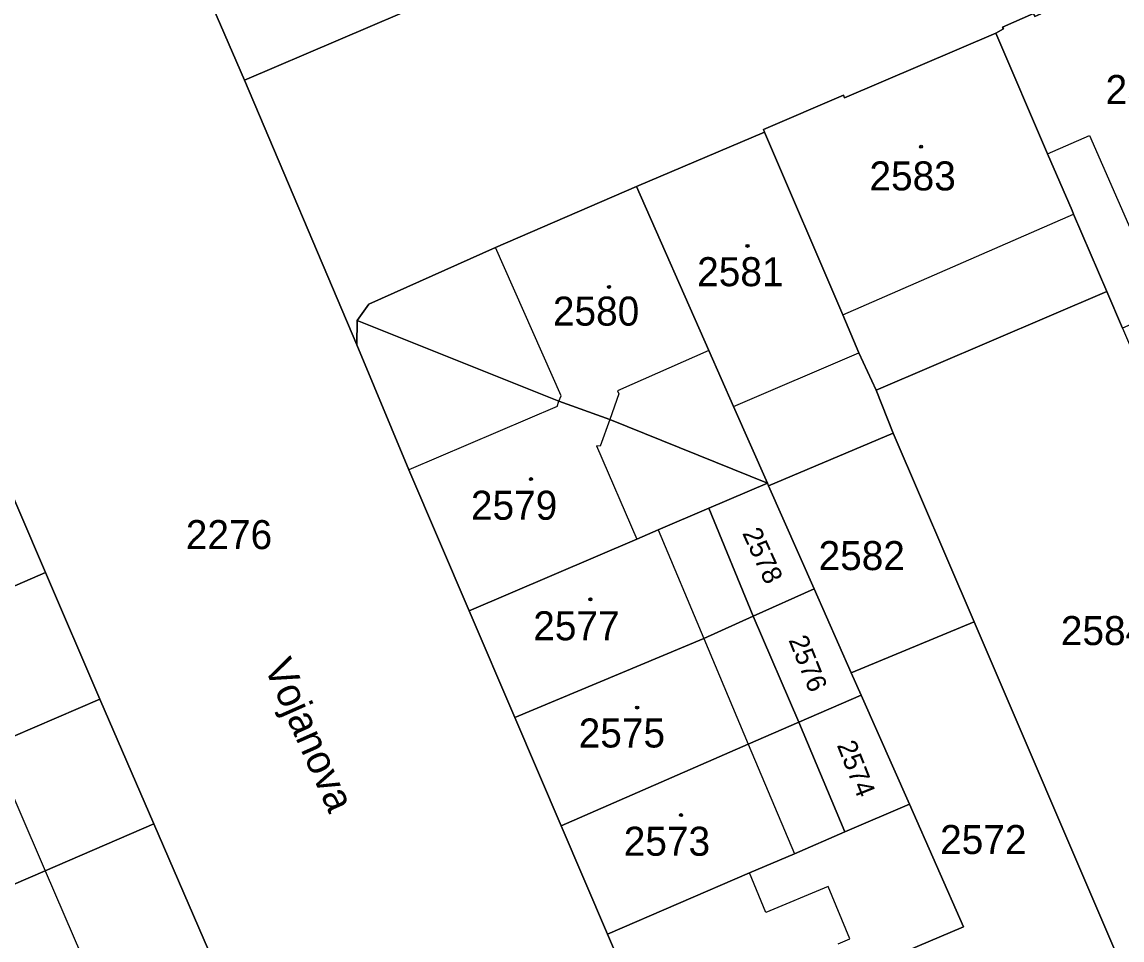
# Model space of a CAD drawing. Extents: x -596233 to -595156, y -1161235 to -1159375.
# Drawn here: x -595851.8 to -595787.4, y -1160619.4 to -1160565.6 of the extents above; entities that cross this region are included whole.
import ezdxf

# ---------------------------------------------------------------- set-up
doc = ezdxf.new("R2010")
doc.units = 0
for name, color, linetype in [('KN_CAR_KR', 7, 'Continuous'), ('KN_KULTURY', 7, 'Continuous'), ('KN_PARC_CIS_POZ', 7, 'Continuous'), ('KN_PARC_CIS_STAV', 7, 'Continuous'), ('KN_PARC_PLOCHA', 7, 'Continuous'), ('KN_ULICE', 7, 'Continuous'), ('parcely_l', 7, 'Continuous')]:
    doc.layers.add(name, color=color, linetype=linetype)

msp = doc.modelspace()

# ---------------------------------------------------------------- linework, layer by layer
at = {"layer": 'KN_CAR_KR'}
for points in [[(-595791.74, -1160573.35), (-595789.28, -1160572.29)], [(-595789.28, -1160572.29), (-595786.87, -1160577.8)], [(-595803.74, -1160582.79), (-595790.22, -1160576.89)], [(-595820.24, -1160587.53), (-595824.08, -1160578.85)], [(-595811.58, -1160584.87), (-595816.93, -1160587.23)], [(-595810.13, -1160588.16), (-595802.79, -1160585.02)], [(-595816.93, -1160587.23), (-595816.85, -1160587.41)], [(-595820.47, -1160588.15), (-595820.36, -1160587.84)], [(-595820.36, -1160587.84), (-595820.24, -1160587.53)], [(-595816.85, -1160587.41), (-595817.39, -1160588.92)], [(-595820.47, -1160588.15), (-595829.16, -1160591.86)], [(-595817.39, -1160588.92), (-595817.94, -1160590.47)], [(-595817.94, -1160590.47), (-595818.16, -1160590.46)], [(-595818.16, -1160590.46), (-595815.81, -1160595.93)], [(-595814.55, -1160595.38), (-595811.88, -1160601.75)], [(-595811.88, -1160601.75), (-595809.27, -1160607.94)], [(-595809.27, -1160607.94), (-595806.57, -1160614.35)], [(-595853.61, -1160608.04), (-595850.46, -1160615.35)], [(-595850.46, -1160615.35), (-595847.24, -1160622.83)], [(-595808.25, -1160617.79), (-595809.21, -1160615.48)], [(-595804.59, -1160616.27), (-595808.25, -1160617.79)], [(-595803.32, -1160619.34), (-595804.59, -1160616.27)], [(-595804, -1160619.62), (-595803.32, -1160619.34)]]:
    msp.add_lwpolyline(points, dxfattribs=at)
at = {"layer": 'KN_KULTURY'}
for centre, radius in [((-595799.15, -1160572.94), 0.09), ((-595799.15, -1160572.94), 0.0398), ((-595809.32, -1160578.75), 0.09), ((-595809.32, -1160578.75), 0.0398), ((-595817.43, -1160581.15), 0.09), ((-595817.43, -1160581.15), 0.0398), ((-595822, -1160592.41), 0.09), ((-595822, -1160592.41), 0.0398), ((-595818.52, -1160599.45), 0.09), ((-595818.52, -1160599.45), 0.0398), ((-595815.78, -1160605.79), 0.09), ((-595815.78, -1160605.79), 0.0398), ((-595813.21, -1160612.09), 0.09), ((-595813.21, -1160612.09), 0.0398)]:
    msp.add_circle(centre, radius, dxfattribs=at)
at = {"layer": 'KN_PARC_PLOCHA'}
for points in [[(-595828.6, -1160546.22), (-595824.7, -1160554.71), (-595830.71, -1160557.42), (-595827.81, -1160564.34), (-595838.78, -1160569.04), (-595848.56, -1160546.48), (-595844.18, -1160544.58), (-595838.57, -1160542.19), (-595839.89, -1160539.16), (-595839.66, -1160539.06), (-595843.45, -1160530.21), (-595843.18, -1160530.1), (-595844.25, -1160527.51), (-595840.67, -1160526.1), (-595846.8, -1160512.82), (-595844.83, -1160511.87)], [(-595773.74, -1160576.54), (-595773.38, -1160577.4), (-595787.35, -1160583.57), (-595788.27, -1160581.43), (-595790.22, -1160576.89), (-595790.31, -1160576.67), (-595791.74, -1160573.35), (-595794.77, -1160566.29), (-595794.33, -1160566.04), (-595794.38, -1160565.93), (-595792.56, -1160565.14), (-595792.49, -1160565.31), (-595792.13, -1160565.16), (-595792.2, -1160564.99), (-595785.13, -1160561.88), (-595785.06, -1160562.03), (-595780.8, -1160560.17), (-595775.75, -1160571.89)], [(-595788.27, -1160581.43), (-595801.78, -1160587.2), (-595802.79, -1160585.02), (-595803.74, -1160582.79), (-595808.33, -1160572.08), (-595808.39, -1160571.94), (-595803.7, -1160569.93), (-595803.64, -1160570.07), (-595794.77, -1160566.29), (-595791.74, -1160573.35), (-595790.31, -1160576.67), (-595790.22, -1160576.89)], [(-595801.78, -1160587.2), (-595800.78, -1160589.71), (-595808.08, -1160592.8), (-595808.15, -1160592.64), (-595810.13, -1160588.16), (-595811.58, -1160584.87), (-595815.82, -1160575.28), (-595808.33, -1160572.08), (-595803.74, -1160582.79), (-595802.79, -1160585.02)], [(-595808.15, -1160592.64), (-595817.39, -1160588.92), (-595820.36, -1160587.84), (-595832.18, -1160583.11), (-595831.5, -1160582.16), (-595824.08, -1160578.85), (-595815.82, -1160575.28), (-595811.58, -1160584.87), (-595810.13, -1160588.16)], [(-595787.35, -1160583.57), (-595774.09, -1160614.44), (-595785.74, -1160619.46), (-595787.69, -1160620.28), (-595796.04, -1160600.77), (-595800.78, -1160589.71), (-595801.78, -1160587.2), (-595788.27, -1160581.43)], [(-595808.15, -1160592.64), (-595811.59, -1160594.11), (-595814.55, -1160595.38), (-595815.81, -1160595.93), (-595825.62, -1160600.13), (-595829.16, -1160591.86), (-595832.2, -1160584.55), (-595832.18, -1160583.11), (-595820.36, -1160587.84), (-595817.39, -1160588.92)], [(-595796.04, -1160600.77), (-595803.24, -1160603.75), (-595805.41, -1160598.83), (-595808.08, -1160592.8), (-595800.78, -1160589.71)], [(-595850.43, -1160597.88), (-595856.78, -1160600.64), (-595865.21, -1160604.3), (-595868.97, -1160605.93), (-595871.65, -1160598.48), (-595868.26, -1160597), (-595859.91, -1160593.35), (-595853.57, -1160590.58)], [(-595808.08, -1160592.8), (-595805.41, -1160598.83), (-595808.98, -1160600.44), (-595811.59, -1160594.11), (-595808.15, -1160592.64)], [(-595808.98, -1160600.44), (-595811.88, -1160601.75), (-595822.95, -1160606.37), (-595825.62, -1160600.13), (-595815.81, -1160595.93), (-595814.55, -1160595.38), (-595811.59, -1160594.11)], [(-595847.25, -1160605.29), (-595853.61, -1160608.04), (-595862.1, -1160611.7), (-595866.23, -1160613.48), (-595869.29, -1160606.07), (-595868.97, -1160605.93), (-595865.21, -1160604.3), (-595856.78, -1160600.64), (-595850.43, -1160597.88)], [(-595803.24, -1160603.75), (-595802.66, -1160605.06), (-595806.32, -1160606.65), (-595808.98, -1160600.44), (-595805.41, -1160598.83)], [(-595806.32, -1160606.65), (-595809.27, -1160607.94), (-595820.24, -1160612.71), (-595822.95, -1160606.37), (-595811.88, -1160601.75), (-595808.98, -1160600.44)], [(-595787.69, -1160620.28), (-595797.48, -1160624.38), (-595801.35, -1160626), (-595803.25, -1160621.42), (-595796.66, -1160618.63), (-595799.84, -1160611.45), (-595802.66, -1160605.06), (-595803.24, -1160603.75), (-595796.04, -1160600.77)], [(-595844.08, -1160612.6), (-595850.46, -1160615.35), (-595858.89, -1160618.98), (-595863.02, -1160620.76), (-595866.23, -1160613.48), (-595862.1, -1160611.7), (-595853.61, -1160608.04), (-595847.25, -1160605.29)], [(-595799.84, -1160611.45), (-595803.61, -1160613.07), (-595806.32, -1160606.65), (-595802.66, -1160605.06)], [(-595803.61, -1160613.07), (-595806.57, -1160614.35), (-595809.21, -1160615.48), (-595817.52, -1160619.06), (-595820.24, -1160612.71), (-595809.27, -1160607.94), (-595806.32, -1160606.65)], [(-595801.35, -1160626), (-595801.57, -1160626.1), (-595802.5, -1160626.5), (-595812.49, -1160630.81), (-595817.52, -1160619.06), (-595809.21, -1160615.48), (-595806.57, -1160614.35), (-595803.61, -1160613.07), (-595799.84, -1160611.45), (-595796.66, -1160618.63), (-595803.25, -1160621.42)], [(-595840.89, -1160620), (-595847.24, -1160622.83), (-595855.67, -1160626.59), (-595858.09, -1160627.67), (-595859.78, -1160628.38), (-595863.02, -1160620.76), (-595858.89, -1160618.98), (-595850.46, -1160615.35), (-595844.08, -1160612.6)]]:
    msp.add_lwpolyline(points, close=True, dxfattribs=at)
for points in [[(-595853.68, -1160534.62), (-595849.94, -1160543.33), (-595848.56, -1160546.48), (-595838.78, -1160569.04), (-595832.2, -1160584.55), (-595829.16, -1160591.86), (-595825.62, -1160600.13), (-595822.95, -1160606.37), (-595820.24, -1160612.71), (-595817.52, -1160619.06), (-595812.49, -1160630.81)], [(-595792.56, -1160565.14), (-595794.38, -1160565.93), (-595794.33, -1160566.04), (-595794.77, -1160566.29), (-595803.64, -1160570.07), (-595803.7, -1160569.93), (-595808.39, -1160571.94), (-595808.33, -1160572.08), (-595815.82, -1160575.28), (-595824.08, -1160578.85), (-595831.5, -1160582.16), (-595832.18, -1160583.11), (-595832.2, -1160584.55), (-595838.78, -1160569.04), (-595827.81, -1160564.34)], [(-595840.89, -1160620), (-595844.08, -1160612.6), (-595847.25, -1160605.29), (-595850.43, -1160597.88), (-595853.57, -1160590.58)]]:
    msp.add_lwpolyline(points, dxfattribs=at)
at = {"layer": 'parcely_l'}
for points in [[(-595838.78, -1160569.04), (-595848.56, -1160546.48)], [(-595780.8, -1160560.17), (-595785.06, -1160562.03), (-595785.13, -1160561.88), (-595792.2, -1160564.99), (-595792.13, -1160565.16), (-595792.49, -1160565.31), (-595792.56, -1160565.14), (-595794.38, -1160565.93), (-595794.33, -1160566.04), (-595794.77, -1160566.29)], [(-595827.81, -1160564.34), (-595838.78, -1160569.04)], [(-595808.33, -1160572.08), (-595808.39, -1160571.94), (-595803.7, -1160569.93), (-595803.64, -1160570.07), (-595794.77, -1160566.29)], [(-595794.77, -1160566.29), (-595791.74, -1160573.35), (-595790.31, -1160576.67), (-595790.22, -1160576.89), (-595788.27, -1160581.43)], [(-595838.78, -1160569.04), (-595832.2, -1160584.55)], [(-595815.82, -1160575.28), (-595808.33, -1160572.08)], [(-595801.78, -1160587.2), (-595802.79, -1160585.02), (-595803.74, -1160582.79), (-595808.33, -1160572.08)], [(-595815.82, -1160575.28), (-595824.08, -1160578.85), (-595831.5, -1160582.16), (-595832.18, -1160583.11)], [(-595808.15, -1160592.64), (-595810.13, -1160588.16), (-595811.58, -1160584.87), (-595815.82, -1160575.28)], [(-595788.27, -1160581.43), (-595801.78, -1160587.2)], [(-595788.27, -1160581.43), (-595787.35, -1160583.57)], [(-595832.2, -1160584.55), (-595832.18, -1160583.11)], [(-595832.18, -1160583.11), (-595820.36, -1160587.84), (-595817.39, -1160588.92), (-595808.15, -1160592.64)], [(-595832.2, -1160584.55), (-595829.16, -1160591.86), (-595825.62, -1160600.13)], [(-595801.78, -1160587.2), (-595800.78, -1160589.71)], [(-595808.08, -1160592.8), (-595800.78, -1160589.71)], [(-595800.78, -1160589.71), (-595796.04, -1160600.77)], [(-595850.43, -1160597.88), (-595853.57, -1160590.58)], [(-595808.15, -1160592.64), (-595811.59, -1160594.11)], [(-595808.08, -1160592.8), (-595808.15, -1160592.64)], [(-595805.41, -1160598.83), (-595808.08, -1160592.8)], [(-595811.59, -1160594.11), (-595814.55, -1160595.38), (-595815.81, -1160595.93), (-595825.62, -1160600.13)], [(-595811.59, -1160594.11), (-595808.98, -1160600.44)], [(-595850.43, -1160597.88), (-595856.78, -1160600.64), (-595865.21, -1160604.3), (-595868.97, -1160605.93)], [(-595847.25, -1160605.29), (-595850.43, -1160597.88)], [(-595808.98, -1160600.44), (-595805.41, -1160598.83)], [(-595805.41, -1160598.83), (-595803.24, -1160603.75)], [(-595825.62, -1160600.13), (-595822.95, -1160606.37)], [(-595822.95, -1160606.37), (-595811.88, -1160601.75), (-595808.98, -1160600.44)], [(-595808.98, -1160600.44), (-595806.32, -1160606.65)], [(-595796.04, -1160600.77), (-595803.24, -1160603.75)], [(-595787.69, -1160620.28), (-595796.04, -1160600.77)], [(-595803.24, -1160603.75), (-595802.66, -1160605.06)], [(-595847.25, -1160605.29), (-595853.61, -1160608.04), (-595862.1, -1160611.7), (-595866.23, -1160613.48)], [(-595844.08, -1160612.6), (-595847.25, -1160605.29)], [(-595802.66, -1160605.06), (-595806.32, -1160606.65)], [(-595802.66, -1160605.06), (-595799.84, -1160611.45)], [(-595820.24, -1160612.71), (-595822.95, -1160606.37)], [(-595806.32, -1160606.65), (-595809.27, -1160607.94), (-595820.24, -1160612.71)], [(-595803.61, -1160613.07), (-595806.32, -1160606.65)], [(-595799.84, -1160611.45), (-595803.61, -1160613.07)], [(-595799.84, -1160611.45), (-595796.66, -1160618.63), (-595803.25, -1160621.42), (-595801.35, -1160626)], [(-595844.08, -1160612.6), (-595850.46, -1160615.35), (-595858.89, -1160618.98), (-595863.02, -1160620.76)], [(-595840.89, -1160620), (-595844.08, -1160612.6)], [(-595820.24, -1160612.71), (-595817.52, -1160619.06)], [(-595803.61, -1160613.07), (-595806.57, -1160614.35), (-595809.21, -1160615.48), (-595817.52, -1160619.06)], [(-595817.52, -1160619.06), (-595812.49, -1160630.81)]]:
    msp.add_lwpolyline(points, dxfattribs=at)

# ---------------------------------------------------------------- texts
at = {"layer": 'KN_PARC_CIS_POZ'}
for s, p in [('2276', (-595842.2166, -1160596.51)), ('2582', (-595805.1566, -1160597.74)), ('2584', (-595790.9666, -1160602.13)), ('2572', (-595798.0366, -1160614.37))]:
    msp.add_text(s, height=1.7, dxfattribs=at).set_placement(p)
for s, rotation, p in [('2578', 294.485549, (-595809.6462, -1160595.568)), ('2576', 291.850874, (-595806.9279, -1160601.8302)), ('2574', 291.559676, (-595804.098, -1160607.9862))]:
    msp.add_text(s, height=1.14, rotation=rotation, dxfattribs=at).set_placement(p)
at = {"layer": 'KN_PARC_CIS_STAV'}
for s, p in [('2585', (-595788.3466, -1160570.44)), ('2583', (-595802.1766, -1160575.5)), ('2581', (-595812.2666, -1160581.11)), ('2580', (-595820.7166, -1160583.42)), ('2579', (-595825.5166, -1160594.79)), ('2577', (-595821.8666, -1160601.85)), ('2575', (-595819.2066, -1160608.13)), ('2573', (-595816.5666, -1160614.47))]:
    msp.add_text(s, height=1.7, dxfattribs=at).set_placement(p)
at = {"layer": 'KN_ULICE'}
msp.add_text('Vojanova', height=1.7, rotation=293.922622, dxfattribs=at).set_placement((-595837.6525, -1160603.3932))

doc.saveas('drawing.dxf')
